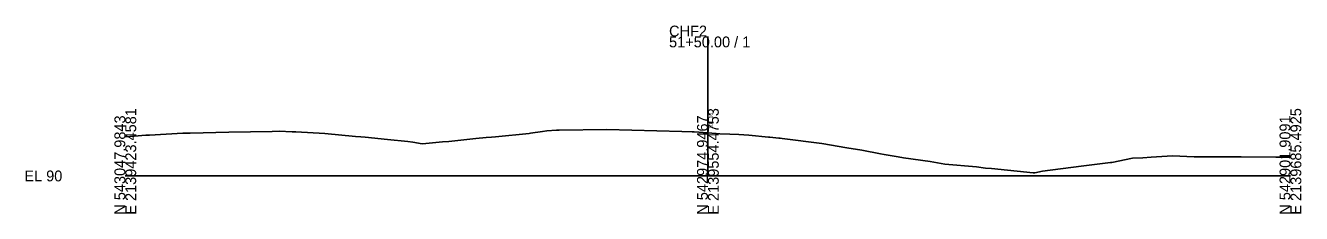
# Model space of a CAD drawing. Extents: x -12831 to 2303, y -10 to 39065.
# Drawn here: x 1974.3 to 2302.8, y 2990.3 to 3038.8 of the extents above; entities that cross this region are included whole.
import ezdxf

# ---------------------------------------------------------------- set-up
doc = ezdxf.new("R2010")
doc.units = 0
for name, color, linetype in [('RD_GPK_XS_Cell', 7, 'Continuous'), ('RD_XS_ExGround', 7, 'Continuous'), ('RD_XS_TX_Elev_EX', 7, 'Continuous')]:
    doc.layers.add(name, color=color, linetype=linetype)

msp = doc.modelspace()

# ---------------------------------------------------------------- linework, layer by layer
at = {"layer": 'RD_GPK_XS_Cell'}
for p, q in [((2150, 3000), (2150, 3035.96)), ((2000, 3000), (2150, 3000)), ((2150, 3000), (2300, 3000))]:
    msp.add_line(p, q, dxfattribs=at)
at = {"layer": 'RD_XS_ExGround'}
for p, q in [((2000, 3010.1), (2002.27, 3010.27)), ((2002.27, 3010.27), (2005.27, 3010.48)), ((2005.27, 3010.48), (2006.2, 3010.53)), ((2006.2, 3010.53), (2014.84, 3011.01)), ((2014.84, 3011.01), (2016.66, 3011.06)), ((2016.66, 3011.06), (2026.68, 3011.26)), ((2026.68, 3011.26), (2037.81, 3011.49)), ((2037.81, 3011.49), (2039.61, 3011.53)), ((2039.61, 3011.53), (2043, 3011.38)), ((2043, 3011.38), (2043.94, 3011.33)), ((2043.94, 3011.33), (2051.4, 3010.96)), ((2051.4, 3010.96), (2059.27, 3010.21)), ((2059.27, 3010.21), (2060.68, 3010.09)), ((2060.68, 3010.09), (2061.74, 3009.99)), ((2061.74, 3009.99), (2067.54, 3009.39)), ((2067.54, 3009.39), (2072.71, 3008.9)), ((2083.28, 3008.92), (2090.28, 3009.65)), ((2090.28, 3009.65), (2092.95, 3009.89)), ((2092.95, 3009.89), (2094.27, 3010)), ((2094.27, 3010), (2095.33, 3010.1)), ((2095.33, 3010.1), (2103.96, 3010.93)), ((2103.96, 3010.93), (2104.37, 3010.99)), ((2104.37, 3010.99), (2107.46, 3011.47)), ((2107.46, 3011.47), (2108.57, 3011.67)), ((2108.57, 3011.67), (2110.99, 3011.78)), ((2110.99, 3011.78), (2111.69, 3011.79)), ((2111.69, 3011.79), (2123.98, 3011.99)), ((2123.98, 3011.99), (2143.27, 3011.46)), ((2143.27, 3011.46), (2145.94, 3011.39)), ((2145.94, 3011.39), (2146.49, 3011.37)), ((2146.49, 3011.37), (2150, 3011.1)), ((2150, 3011.1), (2153.08, 3010.86)), ((2153.08, 3010.86), (2155.63, 3010.75)), ((2155.63, 3010.75), (2157.99, 3010.65)), ((2157.99, 3010.65), (2160.55, 3010.52)), ((2160.55, 3010.52), (2165.65, 3010.04)), ((2165.65, 3010.04), (2165.96, 3009.98)), ((2165.96, 3009.98), (2168.26, 3009.77)), ((2168.26, 3009.77), (2168.57, 3009.73)), ((2168.57, 3009.73), (2169.16, 3009.65)), ((2169.16, 3009.65), (2179.32, 3008.35)), ((2072.71, 3008.9), (2074.02, 3008.68)), ((2074.02, 3008.68), (2076.45, 3008.31)), ((2076.45, 3008.31), (2077.37, 3008.39)), ((2077.37, 3008.39), (2081.7, 3008.77)), ((2081.7, 3008.77), (2083.28, 3008.92)), ((2179.32, 3008.35), (2185.77, 3007.28)), ((2185.77, 3007.28), (2189.62, 3006.65)), ((2189.62, 3006.65), (2194.41, 3005.7)), ((2194.41, 3005.7), (2195.38, 3005.5)), ((2195.38, 3005.5), (2199.02, 3004.9)), ((2199.02, 3004.9), (2200.39, 3004.7)), ((2200.39, 3004.7), (2207.21, 3003.7)), ((2207.21, 3003.7), (2211.05, 3003.07)), ((2211.05, 3003.07), (2219.13, 3002.32)), ((2246.09, 3002.5), (2253.65, 3003.44)), ((2253.65, 3003.44), (2254.01, 3003.48)), ((2254.01, 3003.48), (2259.36, 3004.56)), ((2259.36, 3004.56), (2261.97, 3004.69)), ((2261.97, 3004.69), (2264.15, 3004.83)), ((2264.15, 3004.83), (2269.65, 3005.15)), ((2269.65, 3005.15), (2275.2, 3004.93)), ((2275.2, 3004.93), (2283.79, 3004.92)), ((2283.79, 3004.92), (2285.44, 3004.93)), ((2285.44, 3004.93), (2287.31, 3004.93)), ((2287.31, 3004.93), (2296.25, 3004.8)), ((2296.25, 3004.8), (2298.96, 3004.82)), ((2298.96, 3004.82), (2300, 3004.86)), ((2219.13, 3002.32), (2221.48, 3002)), ((2221.48, 3002), (2223.04, 3001.93)), ((2223.04, 3001.93), (2233.78, 3000.82)), ((2233.78, 3000.82), (2234.16, 3000.82)), ((2234.16, 3000.82), (2236.2, 3001.19)), ((2236.2, 3001.19), (2246.09, 3002.5))]:
    msp.add_line(p, q, dxfattribs=at)

# ---------------------------------------------------------------- texts
at = {"layer": 'RD_GPK_XS_Cell'}
for s, p in [('51+50.00 / 1', (2140, 3033.16)), ('CHF2', (2140, 3035.96)), ('EL 90', (1974, 2998.6))]:
    msp.add_text(s, height=2.8, dxfattribs=at).set_placement(p)
for s, p in [('E 2139423.4581', (2002.8, 2990)), ('E 2139554.4753', (2152.8, 2990)), ('E 2139685.4925', (2302.8, 2990)), ('N 543047.9843', (2000, 2990)), ('N 542974.9467', (2150, 2990)), ('N 542901.9091', (2300, 2990))]:
    msp.add_text(s, height=2.8, rotation=90, dxfattribs=at).set_placement(p)
at = {"layer": 'RD_XS_TX_Elev_EX'}
msp.add_text('101.10', height=1, rotation=90, dxfattribs=at).set_placement((2151.25, 3012.1))

doc.saveas('drawing.dxf')
